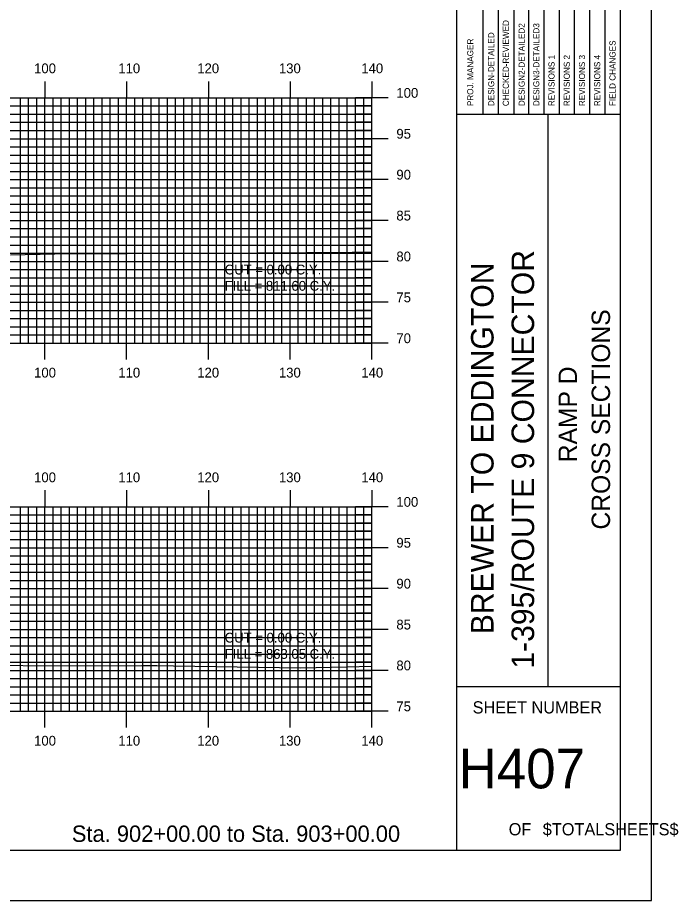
# Model space of a CAD drawing. Extents: x 856716 to 857060, y 364765 to 364985.
# Drawn here: x 856978.9 to 857059.8, y 364765.2 to 364873.1 of the extents above; entities that cross this region are included whole.
import ezdxf

# ---------------------------------------------------------------- set-up
doc = ezdxf.new("R2010")
doc.units = 0
for name, color, linetype in [('BORDER', 7, 'Continuous'), ('D_Text_Standard', 7, 'Continuous'), ('H_V ANNOTATION', 7, 'Continuous'), ('MAJOR', 7, 'Continuous'), ('MINOR', 7, 'Continuous'), ('PLOT BOUNDARY', 7, 'Continuous'), ('S_Roadway_Centerline', 7, 'Continuous')]:
    doc.layers.add(name, color=color, linetype=linetype)

msp = doc.modelspace()

# ---------------------------------------------------------------- linework, layer by layer
at = {"layer": 'BORDER'}
for p, q in [((857032.68, 364771.3), (857032.68, 364981.3)), ((857032.68, 364861.31), (857052.68, 364861.31)), ((857043.86, 364791.31), (857043.86, 364861.31)), ((857032.68, 364791.31), (857052.68, 364791.31))]:
    msp.add_line(p, q, dxfattribs=at)
msp.add_lwpolyline([(856732.68, 364771.3), (857052.68, 364771.3), (857052.68, 364981.3), (856732.68, 364981.3)], close=True, dxfattribs=at)
for points in [[(857037.78, 364861.31), (857037.78, 364896.31)], [(857039.64, 364896.31), (857039.64, 364861.31)], [(857041.5, 364861.31), (857041.5, 364896.31)], [(857043.37, 364861.31), (857043.37, 364896.31)], [(857045.23, 364861.31), (857045.23, 364896.31)], [(857047.09, 364861.31), (857047.09, 364896.31)], [(857048.96, 364861.31), (857048.96, 364896.31)], [(857050.82, 364861.31), (857050.82, 364896.31)], [(857035.91, 364861.31), (857035.91, 364894.9)]]:
    msp.add_lwpolyline(points, dxfattribs=at)
at = {"layer": 'MAJOR'}
for p, q in [((856982.28, 364865.31), (856982.28, 364863.3)), ((856992.28, 364865.31), (856992.28, 364863.3)), ((857002.28, 364865.31), (857002.28, 364863.3)), ((857012.28, 364865.31), (857012.28, 364863.3)), ((857022.28, 364865.31), (857022.28, 364863.3)), ((856742.28, 364863.3), (857022.28, 364863.3)), ((856742.28, 364863.3), (857022.28, 364863.3)), ((856982.28, 364833.3), (856982.28, 364863.3)), ((856992.28, 364833.3), (856992.28, 364863.3)), ((857002.28, 364833.3), (857002.28, 364863.3)), ((857012.28, 364833.3), (857012.28, 364863.3)), ((857024.29, 364863.3), (857020.28, 364863.3)), ((857022.28, 364833.3), (857022.28, 364863.3)), ((857022.28, 364833.3), (857022.28, 364863.3)), ((856742.28, 364858.3), (857022.28, 364858.3)), ((857024.29, 364858.3), (857020.28, 364858.3)), ((856742.28, 364853.3), (857022.28, 364853.3)), ((857024.29, 364853.3), (857020.28, 364853.3)), ((856742.28, 364848.3), (857022.28, 364848.3)), ((857024.29, 364848.3), (857020.28, 364848.3)), ((856742.28, 364843.3), (857022.28, 364843.3)), ((857024.29, 364843.3), (857020.28, 364843.3)), ((856742.28, 364838.3), (857022.28, 364838.3)), ((857024.29, 364838.3), (857020.28, 364838.3)), ((856742.28, 364833.3), (857022.28, 364833.3)), ((856742.28, 364833.3), (857022.28, 364833.3)), ((856982.28, 364831.3), (856982.28, 364833.3)), ((856992.28, 364831.3), (856992.28, 364833.3)), ((857002.28, 364831.3), (857002.28, 364833.3)), ((857012.28, 364831.3), (857012.28, 364833.3)), ((857024.29, 364833.3), (857020.28, 364833.3)), ((857022.28, 364831.3), (857022.28, 364833.3)), ((856982.28, 364815.31), (856982.28, 364813.3)), ((856992.28, 364815.31), (856992.28, 364813.3)), ((857002.28, 364815.31), (857002.28, 364813.3)), ((857012.28, 364815.31), (857012.28, 364813.3)), ((857022.28, 364815.31), (857022.28, 364813.3)), ((856742.28, 364813.3), (857022.28, 364813.3)), ((856742.28, 364813.3), (857022.28, 364813.3)), ((856982.28, 364788.3), (856982.28, 364813.3)), ((856992.28, 364788.3), (856992.28, 364813.3)), ((857002.28, 364788.3), (857002.28, 364813.3)), ((857012.28, 364788.3), (857012.28, 364813.3)), ((857024.29, 364813.3), (857020.28, 364813.3)), ((857022.28, 364788.3), (857022.28, 364813.3)), ((857022.28, 364788.3), (857022.28, 364813.3)), ((856742.28, 364808.3), (857022.28, 364808.3)), ((857024.29, 364808.3), (857020.28, 364808.3)), ((856742.28, 364803.3), (857022.28, 364803.3)), ((857024.29, 364803.3), (857020.28, 364803.3)), ((856742.28, 364798.3), (857022.28, 364798.3)), ((857024.29, 364798.3), (857020.28, 364798.3)), ((856742.28, 364793.3), (857022.28, 364793.3)), ((857024.29, 364793.3), (857020.28, 364793.3)), ((856742.28, 364788.3), (857022.28, 364788.3)), ((856742.28, 364788.3), (857022.28, 364788.3)), ((856982.28, 364786.3), (856982.28, 364788.3)), ((856992.28, 364786.3), (856992.28, 364788.3)), ((857002.28, 364786.3), (857002.28, 364788.3)), ((857012.28, 364786.3), (857012.28, 364788.3)), ((857024.29, 364788.3), (857020.28, 364788.3)), ((857022.28, 364786.3), (857022.28, 364788.3))]:
    msp.add_line(p, q, dxfattribs=at)
at = {"layer": 'MINOR'}
for p, q in [((856979.28, 364833.3), (856979.28, 364863.3)), ((856980.28, 364833.3), (856980.28, 364863.3)), ((856981.28, 364833.3), (856981.28, 364863.3)), ((856983.28, 364833.3), (856983.28, 364863.3)), ((856984.28, 364833.3), (856984.28, 364863.3)), ((856985.28, 364833.3), (856985.28, 364863.3)), ((856986.28, 364833.3), (856986.28, 364863.3)), ((856987.28, 364833.3), (856987.28, 364863.3)), ((856988.28, 364833.3), (856988.28, 364863.3)), ((856989.28, 364833.3), (856989.28, 364863.3)), ((856990.28, 364833.3), (856990.28, 364863.3)), ((856991.28, 364833.3), (856991.28, 364863.3)), ((856993.28, 364833.3), (856993.28, 364863.3)), ((856994.28, 364833.3), (856994.28, 364863.3)), ((856995.28, 364833.3), (856995.28, 364863.3)), ((856996.28, 364833.3), (856996.28, 364863.3)), ((856997.28, 364833.3), (856997.28, 364863.3)), ((856998.28, 364833.3), (856998.28, 364863.3)), ((856999.28, 364833.3), (856999.28, 364863.3)), ((857000.28, 364833.3), (857000.28, 364863.3)), ((857001.28, 364833.3), (857001.28, 364863.3)), ((857003.28, 364833.3), (857003.28, 364863.3)), ((857004.28, 364833.3), (857004.28, 364863.3)), ((857005.28, 364833.3), (857005.28, 364863.3)), ((857006.28, 364833.3), (857006.28, 364863.3)), ((857007.28, 364833.3), (857007.28, 364863.3)), ((857008.28, 364833.3), (857008.28, 364863.3)), ((857009.28, 364833.3), (857009.28, 364863.3)), ((857010.28, 364833.3), (857010.28, 364863.3)), ((857011.28, 364833.3), (857011.28, 364863.3)), ((857013.28, 364833.3), (857013.28, 364863.3)), ((857014.28, 364833.3), (857014.28, 364863.3)), ((857015.28, 364833.3), (857015.28, 364863.3)), ((857016.28, 364833.3), (857016.28, 364863.3)), ((857017.28, 364833.3), (857017.28, 364863.3)), ((857018.28, 364833.3), (857018.28, 364863.3)), ((857019.28, 364833.3), (857019.28, 364863.3)), ((857020.28, 364833.3), (857020.28, 364863.3)), ((857021.28, 364833.3), (857021.28, 364863.3)), ((856742.28, 364862.3), (857022.28, 364862.3)), ((857022.28, 364862.3), (857020.28, 364862.3)), ((856742.28, 364861.3), (857022.28, 364861.3)), ((857022.28, 364861.3), (857020.28, 364861.3)), ((856742.28, 364860.3), (857022.28, 364860.3)), ((856742.28, 364859.3), (857022.28, 364859.3)), ((857022.28, 364860.3), (857020.28, 364860.3)), ((857022.28, 364859.3), (857020.28, 364859.3)), ((856742.28, 364857.3), (857022.28, 364857.3)), ((857022.28, 364857.3), (857020.28, 364857.3)), ((856742.28, 364856.3), (857022.28, 364856.3)), ((857022.28, 364856.3), (857020.28, 364856.3)), ((856742.28, 364855.3), (857022.28, 364855.3)), ((857022.28, 364855.3), (857020.28, 364855.3)), ((856742.28, 364854.3), (857022.28, 364854.3)), ((857022.28, 364854.3), (857020.28, 364854.3)), ((856742.28, 364852.3), (857022.28, 364852.3)), ((857022.28, 364852.3), (857020.28, 364852.3)), ((856742.28, 364851.3), (857022.28, 364851.3)), ((857022.28, 364851.3), (857020.28, 364851.3)), ((856742.28, 364850.3), (857022.28, 364850.3)), ((857022.28, 364850.3), (857020.28, 364850.3)), ((856742.28, 364849.3), (857022.28, 364849.3)), ((857022.28, 364849.3), (857020.28, 364849.3)), ((856742.28, 364847.3), (857022.28, 364847.3)), ((856742.28, 364846.3), (857022.28, 364846.3)), ((857022.28, 364847.3), (857020.28, 364847.3)), ((857022.28, 364846.3), (857020.28, 364846.3)), ((856742.28, 364845.3), (857022.28, 364845.3)), ((857022.28, 364845.3), (857020.28, 364845.3)), ((856742.28, 364844.3), (857022.28, 364844.3)), ((857022.28, 364844.3), (857020.28, 364844.3)), ((856742.28, 364842.3), (857022.28, 364842.3)), ((857022.28, 364842.3), (857020.28, 364842.3)), ((856742.28, 364841.3), (857022.28, 364841.3)), ((857022.28, 364841.3), (857020.28, 364841.3)), ((856742.28, 364840.3), (857022.28, 364840.3)), ((857022.28, 364840.3), (857020.28, 364840.3)), ((856742.28, 364839.3), (857022.28, 364839.3)), ((857022.28, 364839.3), (857020.28, 364839.3)), ((856742.28, 364837.3), (857022.28, 364837.3)), ((857022.28, 364837.3), (857020.28, 364837.3)), ((856742.28, 364836.3), (857022.28, 364836.3)), ((857022.28, 364836.3), (857020.28, 364836.3)), ((856742.28, 364835.3), (857022.28, 364835.3)), ((857022.28, 364835.3), (857020.28, 364835.3)), ((856742.28, 364834.3), (857022.28, 364834.3)), ((857022.28, 364834.3), (857020.28, 364834.3)), ((856979.28, 364788.3), (856979.28, 364813.3)), ((856980.28, 364788.3), (856980.28, 364813.3)), ((856981.28, 364788.3), (856981.28, 364813.3)), ((856983.28, 364788.3), (856983.28, 364813.3)), ((856984.28, 364788.3), (856984.28, 364813.3)), ((856985.28, 364788.3), (856985.28, 364813.3)), ((856986.28, 364788.3), (856986.28, 364813.3)), ((856987.28, 364788.3), (856987.28, 364813.3)), ((856988.28, 364788.3), (856988.28, 364813.3)), ((856989.28, 364788.3), (856989.28, 364813.3)), ((856990.28, 364788.3), (856990.28, 364813.3)), ((856991.28, 364788.3), (856991.28, 364813.3)), ((856993.28, 364788.3), (856993.28, 364813.3)), ((856994.28, 364788.3), (856994.28, 364813.3)), ((856995.28, 364788.3), (856995.28, 364813.3)), ((856996.28, 364788.3), (856996.28, 364813.3)), ((856997.28, 364788.3), (856997.28, 364813.3)), ((856998.28, 364788.3), (856998.28, 364813.3)), ((856999.28, 364788.3), (856999.28, 364813.3)), ((857000.28, 364788.3), (857000.28, 364813.3)), ((857001.28, 364788.3), (857001.28, 364813.3)), ((857003.28, 364788.3), (857003.28, 364813.3)), ((857004.28, 364788.3), (857004.28, 364813.3)), ((857005.28, 364788.3), (857005.28, 364813.3)), ((857006.28, 364788.3), (857006.28, 364813.3)), ((857007.28, 364788.3), (857007.28, 364813.3)), ((857008.28, 364788.3), (857008.28, 364813.3)), ((857009.28, 364788.3), (857009.28, 364813.3)), ((857010.28, 364788.3), (857010.28, 364813.3)), ((857011.28, 364788.3), (857011.28, 364813.3)), ((857013.28, 364788.3), (857013.28, 364813.3)), ((857014.28, 364788.3), (857014.28, 364813.3)), ((857015.28, 364788.3), (857015.28, 364813.3)), ((857016.28, 364788.3), (857016.28, 364813.3)), ((857017.28, 364788.3), (857017.28, 364813.3)), ((857018.28, 364788.3), (857018.28, 364813.3)), ((857019.28, 364788.3), (857019.28, 364813.3)), ((857020.28, 364788.3), (857020.28, 364813.3)), ((857021.28, 364788.3), (857021.28, 364813.3)), ((856742.28, 364812.3), (857022.28, 364812.3)), ((857022.28, 364812.3), (857020.28, 364812.3)), ((856742.28, 364811.3), (857022.28, 364811.3)), ((857022.28, 364811.3), (857020.28, 364811.3)), ((856742.28, 364810.3), (857022.28, 364810.3)), ((857022.28, 364810.3), (857020.28, 364810.3)), ((856742.28, 364809.3), (857022.28, 364809.3)), ((857022.28, 364809.3), (857020.28, 364809.3)), ((856742.28, 364807.3), (857022.28, 364807.3)), ((857022.28, 364807.3), (857020.28, 364807.3)), ((856742.28, 364806.3), (857022.28, 364806.3)), ((856742.28, 364805.3), (857022.28, 364805.3)), ((857022.28, 364806.3), (857020.28, 364806.3)), ((857022.28, 364805.3), (857020.28, 364805.3)), ((856742.28, 364804.3), (857022.28, 364804.3)), ((857022.28, 364804.3), (857020.28, 364804.3)), ((856742.28, 364802.3), (857022.28, 364802.3)), ((857022.28, 364802.3), (857020.28, 364802.3)), ((856742.28, 364801.3), (857022.28, 364801.3)), ((857022.28, 364801.3), (857020.28, 364801.3)), ((856742.28, 364800.3), (857022.28, 364800.3)), ((857022.28, 364800.3), (857020.28, 364800.3)), ((856742.28, 364799.3), (857022.28, 364799.3)), ((857022.28, 364799.3), (857020.28, 364799.3)), ((856742.28, 364797.3), (857022.28, 364797.3)), ((857022.28, 364797.3), (857020.28, 364797.3)), ((856742.28, 364796.3), (857022.28, 364796.3)), ((857022.28, 364796.3), (857020.28, 364796.3)), ((856742.28, 364795.3), (857022.28, 364795.3)), ((857022.28, 364795.3), (857020.28, 364795.3)), ((856742.28, 364794.3), (857022.28, 364794.3)), ((857022.28, 364794.3), (857020.28, 364794.3)), ((856742.28, 364792.3), (857022.28, 364792.3)), ((856742.28, 364791.3), (857022.28, 364791.3)), ((857022.28, 364792.3), (857020.28, 364792.3)), ((857022.28, 364791.3), (857020.28, 364791.3)), ((856742.28, 364790.3), (857022.28, 364790.3)), ((857022.28, 364790.3), (857020.28, 364790.3)), ((856742.28, 364789.3), (857022.28, 364789.3)), ((857022.28, 364789.3), (857020.28, 364789.3))]:
    msp.add_line(p, q, dxfattribs=at)
at = {"layer": 'PLOT BOUNDARY'}
msp.add_lwpolyline([(856716.49, 364765.18), (857056.49, 364765.18), (857056.49, 364985.18), (856716.49, 364985.18)], close=True, dxfattribs=at)
at = {"layer": 'S_Roadway_Centerline'}
for points in [[(856978.09, 364844.11), (856983.51, 364844.22), (857001.19, 364844.31), (857002.39, 364844.32), (857014.34, 364844.38), (857019.87, 364844.43), (857022.28, 364844.44)], [(856853.38, 364795.15), (856867.43, 364794.72), (856881.67, 364794.51), (856885.47, 364794.41), (856897.02, 364794.4), (856903.2, 364794.42), (856918.78, 364794.5), (856921.83, 364794.51), (856933.34, 364794.06), (856940.25, 364793.99), (856945.74, 364794.06), (856956.32, 364794.16), (856958.57, 364794.16), (856960.75, 364794.16), (856976.96, 364793.95), (856982.22, 364793.86), (856994.13, 364793.9), (856995.97, 364793.89), (856998, 364793.85), (857013.61, 364793.61), (857019.2, 364793.75), (857022.28, 364793.83)]]:
    msp.add_lwpolyline(points, dxfattribs=at)

# ---------------------------------------------------------------- texts
at = {"layer": 'BORDER'}
for s, height, p in [('CHECKED-REVIEWED', 0.7455, (857039.04, 364862.28)), ('DESIGN2-DETAILED2', 0.7455, (857040.98, 364862.28)), ('DESIGN3-DETAILED3', 0.7455, (857042.77, 364862.28)), ('DESIGN-DETAILED', 0.7455, (857037.25, 364862.28)), ('PROJ. MANAGER', 0.7455, (857034.69, 364862.28)), ('FIELD CHANGES', 0.7455, (857052.09, 364862.28)), ('REVISIONS 1', 0.7455, (857044.63, 364862.28)), ('REVISIONS 2', 0.7455, (857046.5, 364862.28)), ('REVISIONS 3', 0.7455, (857048.36, 364862.28)), ('REVISIONS 4', 0.7455, (857050.22, 364862.28)), ('1-395/ROUTE 9 CONNECTOR', 2.7557, (857042.13, 364793.5)), ('BREWER TO EDDINGTON', 2.7557, (857037.17, 364797.71)), ('CROSS SECTIONS', 2.25, (857051.42, 364810.52)), ('RAMP D', 2.25, (857047.37, 364818.75))]:
    msp.add_text(s, height=height, rotation=90, dxfattribs=at).set_placement(p)
for s, height, p in [('SHEET NUMBER', 1.4905, (857034.61, 364788.03)), ('H407', 4.839, (857032.89, 364778.87)), ('OF', 1.491, (857039.02, 364773.13)), ('$TOTALSHEETS$', 1.4905, (857043.19, 364773.13))]:
    msp.add_text(s, height=height, dxfattribs=at).set_placement(p)
at = {"layer": 'D_Text_Standard'}
for s, p in [('CUT = 0.00 C.Y.', (857004.28, 364841.7)), ('FILL = 811.60 C.Y.', (857004.28, 364839.71)), ('CUT = 0.00 C.Y.', (857004.28, 364796.7)), ('FILL = 863.05 C.Y.', (857004.28, 364794.71))]:
    msp.add_text(s, height=1.2, dxfattribs=at).set_placement(p)
at = {"layer": 'H_V ANNOTATION'}
for s, height, p in [('100', 1.2, (856980.96, 364866.3)), ('110', 1.2, (856991.26, 364866.3)), ('120', 1.2, (857000.92, 364866.3)), ('130', 1.2, (857010.91, 364866.3)), ('140', 1.2, (857020.99, 364866.3)), ('100', 1.2, (857025.28, 364863.3)), ('95', 1.2, (857025.28, 364858.3)), ('90', 1.2, (857025.28, 364853.3)), ('85', 1.2, (857025.28, 364848.3)), ('80', 1.2, (857025.28, 364843.3)), ('75', 1.2, (857025.28, 364838.3)), ('70', 1.2, (857025.28, 364833.3)), ('100', 1.2, (856980.96, 364829.1)), ('110', 1.2, (856991.26, 364829.1)), ('120', 1.2, (857000.92, 364829.1)), ('130', 1.2, (857010.91, 364829.1)), ('140', 1.2, (857020.99, 364829.1)), ('100', 1.2, (856980.96, 364816.3)), ('110', 1.2, (856991.26, 364816.3)), ('120', 1.2, (857000.92, 364816.3)), ('130', 1.2, (857010.91, 364816.3)), ('140', 1.2, (857020.99, 364816.3)), ('100', 1.2, (857025.28, 364813.3)), ('95', 1.2, (857025.28, 364808.3)), ('90', 1.2, (857025.28, 364803.3)), ('85', 1.2, (857025.28, 364798.3)), ('80', 1.2, (857025.28, 364793.3)), ('75', 1.2, (857025.28, 364788.3)), ('100', 1.2, (856980.96, 364784.1)), ('110', 1.2, (856991.26, 364784.1)), ('120', 1.2, (857000.92, 364784.1)), ('130', 1.2, (857010.91, 364784.1)), ('140', 1.2, (857020.99, 364784.1)), ('Sta. 902+00.00 to Sta. 903+00.00', 2.0004, (856985.58, 364772.33))]:
    msp.add_text(s, height=height, dxfattribs=at).set_placement(p)

doc.saveas('drawing.dxf')
